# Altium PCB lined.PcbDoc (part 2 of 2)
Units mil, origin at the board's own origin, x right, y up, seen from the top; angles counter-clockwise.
Board outline 3500.17 x 4287.12 mil, 2 copper layers (Top Layer, Bottom Layer); 109 components, 117 nets, 494 pads, 325 vias.
Unrouted connection lines stored in the file: 3.
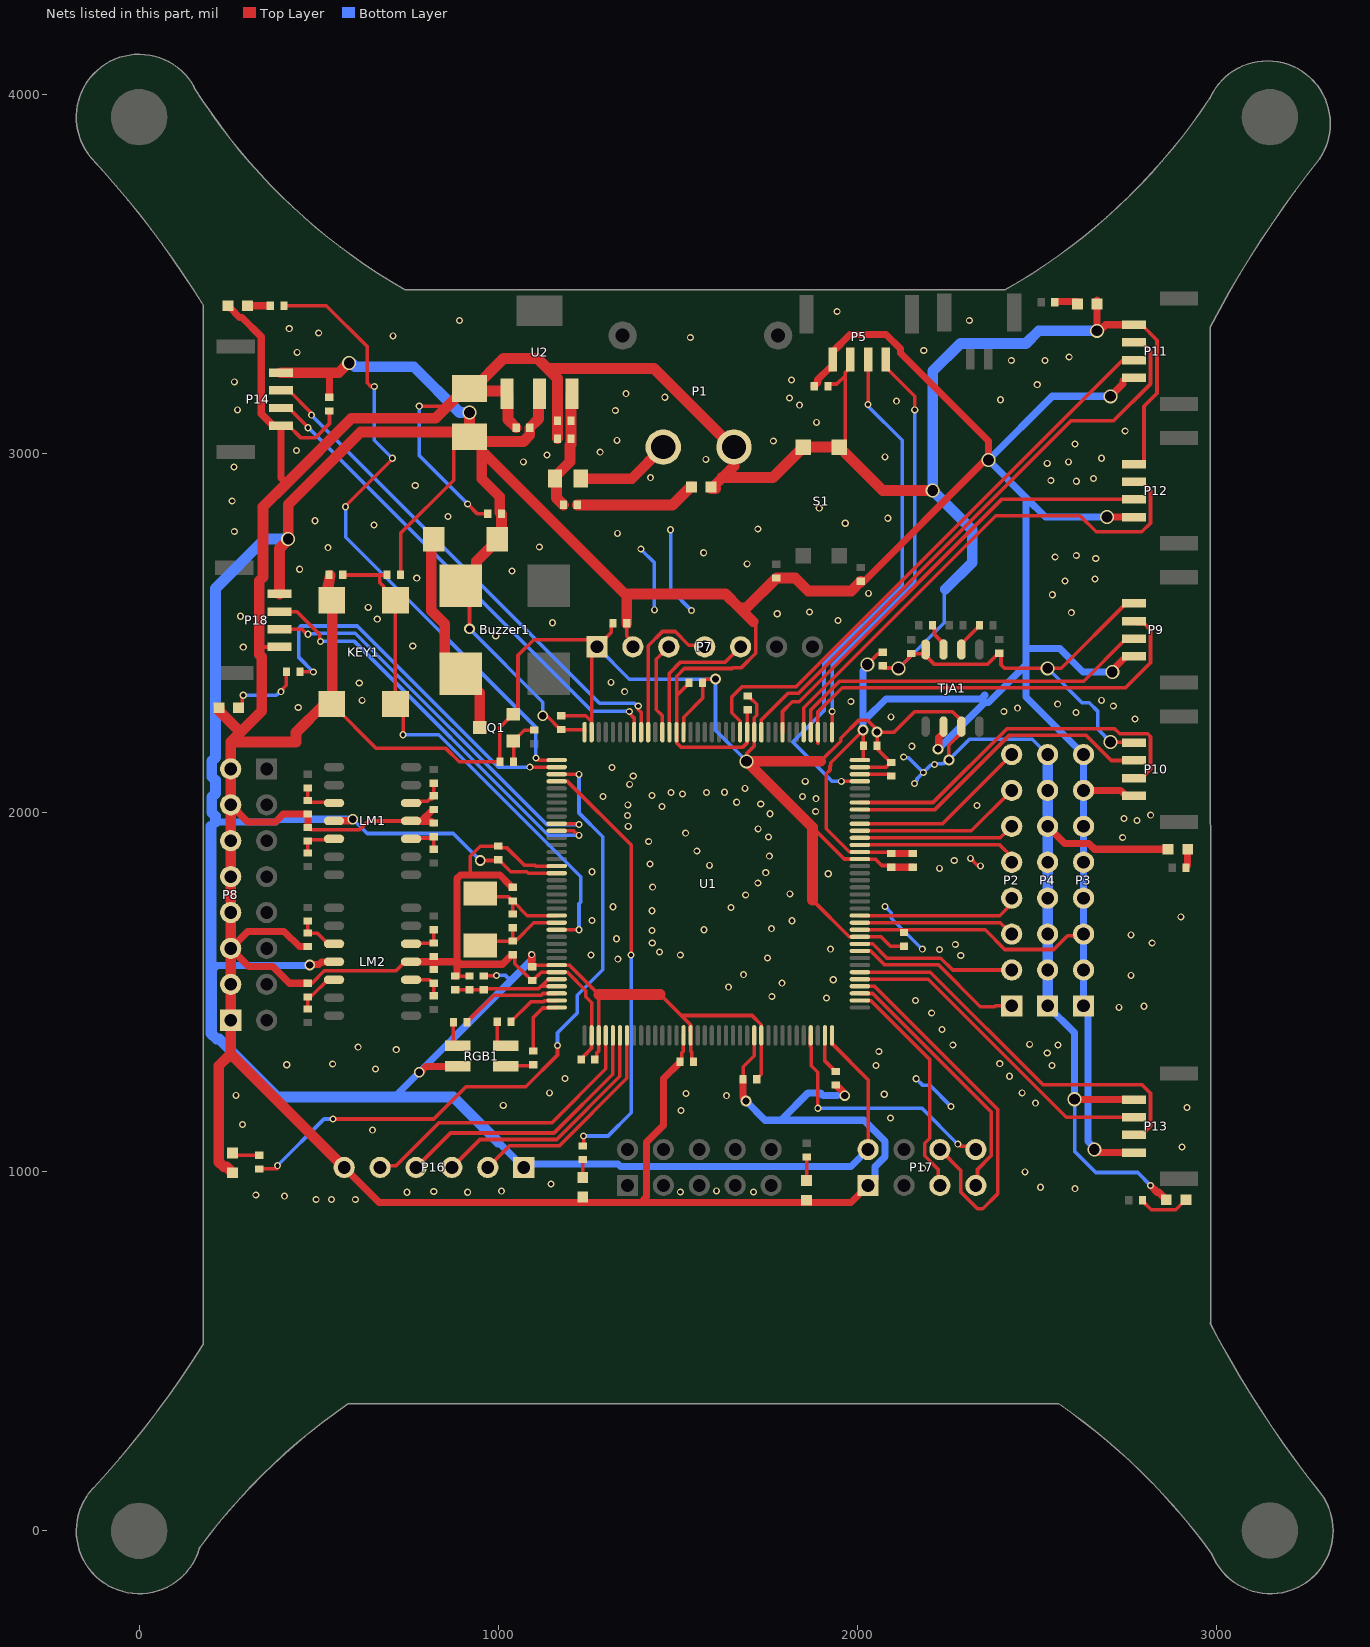
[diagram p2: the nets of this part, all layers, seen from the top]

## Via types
v1: diameter 19.68, hole 11.81, Top Layer to Bottom Layer, tented both sides, 293 vias
v2: diameter 30, hole 20, Top Layer to Bottom Layer, tented both sides, 16 vias
v3: diameter 39, hole 30, Top Layer to Bottom Layer, tented both sides, 16 vias

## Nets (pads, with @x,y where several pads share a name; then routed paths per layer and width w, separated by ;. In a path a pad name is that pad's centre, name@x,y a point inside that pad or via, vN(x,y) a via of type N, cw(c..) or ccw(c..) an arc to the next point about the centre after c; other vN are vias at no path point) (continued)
GND: C1.2 C2.2 C3.2 C4.2 C5.2 C6.2 C7.1 C8.1 C9.2 C10.1 C11.1 C12.1 C13.1 C14.1 C15.1 C16.1 C17.1 C18.1 C19.1 C20.1 C21.1 C22.1 C23.1 C24.1 C25.1 C26.1 C27.1 C28.1 C29.1 E1.2 KEY1.1 KEY1.2 LED1.2 LED2.2 LED3.2 LED4.2 LED5.2 LED6.2 LED7.2 LED8.2 LED9.2 LM1.11 LM2.11 P1.2 P4.1 P4.2 P4.3 P4.4 P4.5 P4.6 P4.7 P4.8 P5.3 P7.1 P8.1 P8.2 P8.3 P8.4 P8.5 P8.6 P8.7 P8.8 P9.4 P10.4 P11.4 P12.4 P13.4 P14.4 P16.6 P17.1 P18.4 Q1.1 R5.1 R6.1 R8.1 R9.1 R15.1 R16.1 R18.1 R19.1 R26.1 S1.1 S1.3 TJA1.3 TJA1.8 U1.16 U1.31 U1.38 U1.51 U1.61 U1.83 U1.94 U1.107 U1.120 U1.130 U1.143 U2.1 | length 25095.4
  Top Layer w10: 334.52,2467 339.99,2461.53 P18.4@390.98,2461.53 ; P14.4@395,3077.79 416.65,3077.79 450.83,3043.61 490,3043.61 530,3083.61 C28.1@530,3119 ; R19.1@469.23,1525.16 481.24,1525.16 515.71,1559.62 715.36,1559.62 740.55,1584.81 LM2.11@757.28,1584.81 ; R9.1@469.97,1959 471.78,1959 478.59,1952.19 613.88,1952.19 638.69,1977 LM1.11@757.28,1977 ; KEY1.1@536.42,2302.32 537.4,2302.32 660.72,2179 854.31,2179 891.31,2142 R26.1@1004.7,2142 1004.7,2237.84 1027.56,2260.7 1027.56,2261.69 1040.28,2274.4 Q1.1@1041.26,2274.4 1042.24,2274.4 1054.96,2287.12 1054.96,2438.16 1098.81,2482 1255,2482 P7.1@1275,2462 ; v1(780,3132) 850,3132 854.27,3127.73 ; C13.1@881.81,1545 C14.1@920,1545 ; v1(915,2859.51) 942.44,2832.06 C12.1@971,2832.06 ; 925,1826.8 922,1829.8 922,1878.6 950.3,1906.9 C22.1@1000,1906.9 1005,1901.9 1024.65,1901.9 1073.04,1853.5 1102.3,1853.5 1104.59,1851.21 U1.16@1162.76,1851.21 ; C2.2@1040,1604.5 1041.3,1604.5 1046.3,1599.5 1046.3,1579.5 1077.8,1548 1078.19,1548 1093.19,1533 C18.1@1095,1533 1096.81,1533 1111.81,1548 1112.2,1548 1119.79,1555.59 1162.41,1555.59 U1.31@1162.76,1555.94 1163.1,1555.59 1192.79,1555.59 1244.13,1504.25 1244.13,1487.16 1260.2,1471.09 1260.2,1382.78 1259.85,1382.43 1259.85,1343.75 1246,1329.9 1246,1329.51 1231,1314.51 C23.1@1231,1312.7 ; C19.1@1175,2270 1244.13,2270 1259.85,2254.28 1259.85,2224.59 U1.143@1260.2,2224.24 1260.2,2447.2 P7.1@1275,2462 ; C8.1@1320,2527 1315,2522 1315,2502 P7.1@1275,2462 ; C24.1@1506,1307 1511,1312 1511,1331.53 1515.76,1336.28 1515.76,1379.41 U1.51@1516.1,1379.76 ; U1.130@1516.1,2224.24 1516.45,2224.59 1516.45,2265.82 1569,2318.37 C25.1@1569,2362.24 1578.76,2372 v2(1605,2372) ; C26.1@1682,1257.58 1682,1292.53 1712.95,1323.49 U1.61@1712.95,1379.76 ; v3(1691.66,2143) 1691.66,2164.89 1712.61,2185.84 1712.61,2223.9 U1.120@1712.95,2224.24 1713.3,2224.59 1713.3,2264.71 1719.81,2271.23 1719.81,2302 1702.2,2319.61 1700,2319.61 C27.1@1695,2324.61 ; 1875,1756.92 1977.21,1654.71 2006.9,1654.71 U1.83@2007.24,1654.36 2066.1,1654.36 2092.46,1628 C20.1@2130,1628 ; 1875,1959.66 1963.7,1870.96 2007.18,1870.96 U1.94@2007.24,1870.9 2007.59,1870.55 2050.72,1870.55 2068.27,1853 2090,1853 C9.2@2095,1848 ; 1897.62,2143 1953.87,2199.25 1953.87,2207.3 2004.57,2258 2027.76,2258 2051.17,2234.59 2051.17,2228.42 v2(2055,2224.59) ; C7.1@1918,3187 1918,3188.78 1923,3193.78 1943,3193.78 1966.46,3217.24 ; S1.3@1949.8,3018.09 1966.46,3001.44 1966.46,3217.24 ; P5.3@1980.79,3262 1980.79,3240.35 1966.46,3226.02 1966.46,3217.24 ; U1.107@2007.24,2126.8 2079.99,2126.8 2093.19,2140 2055,2178.19 C21.1@2055,2187 v2(2055,2224.59) ; C29.1@2070.89,2404 2071.89,2403 2114,2403 v3(2115,2402) 2155.75,2442.75 2183.71,2442.75 TJA1.8@2190,2449.04 ; TJA1.8@2190,2454.48 TJA1.8@2190,2449.04 ; v2(2255,2147) 2255,2188.18 2290,2223.18 TJA1.3@2290,2239.92 2290,2256.65 2265.19,2281.46 2159.46,2281.46 2102.59,2224.59 v2(2055,2224.59) ; v1(2315,1873) 2334.15,1853.85 2341.15,1853.85 v1(2343,1852) ; v3(2667.5,3342) v3@2675,3342 ; v3(2705,2197) 2706.18,2195.82 2768.82,2195.82 P10.4@2770,2194.64 ; P9.4@2770,2582.71 2748.35,2582.71 2567.64,2402 v3(2530,2402) 2410,2402 2400,2412 2400,2439.2 C11.1@2395,2444.2 2393.19,2444.2 2361.93,2412.94 2214.81,2412.94 2190,2437.75 TJA1.8@2190,2449.04 ; P12.4@2770,2970.78 2791.65,2970.78 2798.46,2977.59 2798.46,3132.08 2834.46,3168.08 2834.46,3316.04 2791.65,3358.85 P11.4@2770,3358.85
  Top Layer w20: LED2.2@247.5,3412.06 266.64,3392.92 266.64,3391.9 279.54,3379 286.57,3379 340.17,3325.4 340.17,3110.97 373.35,3077.79 P14.4@395,3077.79 395,2932.1 410,2917.1 ; P8.7@255,2022 302.53,1974.47 379.86,1974.47 401.39,1996 R6.1@469.97,1996 R9.1@469.97,1959 ; R19.1@469.23,1525.16 419.06,1525.16 372.21,1572 305,1572 P8.3@255,1622 302.53,1669.53 403.72,1669.53 446.25,1627 R16.1@469.97,1627 ; P16.6@571,1012 668.53,914.47 1397.47,914.47 ; LM2.11@757.28,1584.81 825,1584.81 ; LM1.11@757.28,1977 757.98,1976.31 812.76,1976.31 818.19,1970.87 R8.1@820,1970.87 ; 786.82,1977.69 818.19,2009.06 R5.1@820,2009.06 ; R18.1@820,1563.16 821.81,1563.16 821.81,1581.62 825,1584.81 ; C13.1@880,1545 881.81,1545 881.81,1546.81 884.76,1549.76 884.76,1588.75 ; C2.2@1040,1604.5 1038.19,1604.5 1011.89,1578.2 895.3,1578.2 884.76,1588.75 ; C1.2@1040,1792.5 1038.19,1792.5 1018.84,1811.85 1018.84,1812.66 1004.7,1826.8 925,1826.8 895.3,1826.8 884.76,1816.26 884.76,1588.75 ; C24.1@1506,1307 1506,1305.19 1460.36,1259.55 1460.36,1129.58 1412.47,1081.69 1412.47,929.47 1397.47,914.47 ; C26.1@1682,1257.58 1682,1207.71 1690,1199.71 v2(1690,1197) ; C16.1@1939.77,1241.28 1941.58,1241.28 1962.85,1220 1962.85,1213.91 v2(1964.77,1212) ; P17.1@2030,962 1982.19,914.19 1942.81,914.19 1942.53,914.47 1397.47,914.47 ; C9.2@2095,1848 C17.1@2155,1848 ; P4.6@2530,1962 2577.53,1914.47 2644.74,1914.47 2661.09,1898.13 LED7.2@2865.5,1898.13 ; v3@2605,1201.21 P13.4@2770,1201.21 ; v3(2667.5,3342) LED6.2@2667.5,3416.94 LED6.2@2667.5,3426.94 ; v3@2675,3342 2691.85,3358.85 P11.4@2770,3358.85 ; v1(2816.46,962) 2835.38,943.06 2839.49,943.06 LED8.2@2860.48,922.06 ; 825,1584.81 880.82,1584.81 884.76,1588.75
  Top Layer w30: LED3.2@222.5,2292.06 222.5,2283.97 276.97,2229.5 287.5,2229.5 ; LED4.2@259.94,997.5 243.44,1014 235.47,1014 222,1027.47 222,1295 255,1328 ; KEY1.1@515.73,2302 436.85,2223.12 436.85,2197 255,2197 ; KEY1.2@525.98,2600.64 525.98,2628.56 C6.2@532.34,2661.35 ; KEY1.1@536.42,2302.32 537.84,2303.74 537.84,2590.26 KEY1.2@536.42,2591.69 ; P16.6@571,1012 255,1328 ; C3.2@1050,3072 1027.17,3094.83 1027.17,3163.93 U2.1@1024.45,3166.65 1024.45,3171.43 1021.73,3174.15 927.5,3174.15 E1.2@920,3181.65 ; C5.2@1165,3042 C4.2@1165,3092 1164.83,3092.17 1164.83,3209.38 1137.21,3237 ; LED1.2@1605,2902 1593.5,2902 1656.43,2964.93 1656.43,3014.57 1434,3237 1137.21,3237 ; 1623,2933.3 1765.01,2933.3 S1.1@1849.8,3018.09 S1.3@1949.8,3018.09 ; 1875,1756.92 1875,1959.66 v3(1691.66,2143) 1897.62,2143 ; S1.3@1966.46,3001.44 2070.89,2897 v3(2210,2897) ; 255,1328 P8.1@255,1422 P8.2@255,1522 P8.3@255,1622 P8.4@255,1722 P8.5@255,1822 P8.6@255,1922 P8.7@255,2022 P8.8@255,2122 255,2197 ; 255,2197 287.5,2229.5 ; 287.5,2229.5 341.15,2283.15 341.15,2433.56 334.52,2440.19 334.52,2467 334.52,2646.16 344.93,2656.56 344.93,2852.03 410,2917.1 591.32,3098.43 824.97,3098.43 854.27,3127.73 908.19,3181.65 E1.2@920,3181.65 ; E1.2@920,3181.65 931.81,3181.65 1014.74,3264.57 1109.64,3264.57 1137.21,3237
  Bottom Layer w10: v1(780,3132) 780,2994.51 v1(915,2859.51) ; P7.1@1275,2462 1365,2372 v2(1605,2372) 1605,2229.66 v3(1691.66,2143) ; v1(1397,2734) 1435,2696 v1(1435,2565) ; v1(1480,2788) 1480,2621 v1(1538,2563) ; v1(2077,1739) 2094.57,1721.43 2094.57,1706.43 v1(2181,1620) ; v3(2115,2402) 2242.16,2529.16 2242.16,2619.16 2245,2622 ; v1(2129,2155) 2130.85,2153.15 2142.56,2153.15 v1(2183.71,2112) ; v1(2159,2081) 2159,2083.62 2166.14,2090.76 2166.14,2094.43 v1(2183.71,2112) ; v1(2164,1259) 2181.57,1241.43 2201.57,1241.43 v1(2261,1182) ; P4.8@2530,2162 2487.47,2204.53 2312.53,2204.53 v2(2255,2147) 2249.59,2147 2238.44,2135.85 2216.66,2135.85 v1(2214.81,2134) 2212.96,2132.15 2203.85,2132.15 v1(2183.71,2112) ; v3(2530,2402) 2625.6,2306.4 2645.6,2306.4 2670,2282 2670,2232 v3(2705,2197) ; v3(2605,1202) 2605,1057 2664.07,997.93 2780.54,997.93 v1(2816.46,962)
  Bottom Layer w20: v2(1690,1197) 1743.28,1143.72 1790,1143.72 ; 1945,1212 1904.38,1212 1896.53,1219.84 1863.47,1219.84 1790,1146.38 1790,1143.72 ; P17.1@2030,962 2049.53,981.53 2049.53,1014.31 2077.53,1042.31 2077.53,1084.47 2018.28,1143.72 1790,1143.72 ; P4.1@2530,1462 2605,1387 v3(2605,1202)
  Bottom Layer w30: 2245,2622 2320,2697 2320,2787 v3(2210,2897) 2210,3229.84 2287.16,3307 2470,3307 2505,3342 v3(2667.5,3342) ; P4.1@2530,1462 P4.2@2530,1562 P4.3@2530,1662 P4.4@2530,1762 P4.5@2530,1862 P4.6@2530,1962 P4.7@2530,2062 P4.8@2530,2162
  other v1: 493,923 536,923 602,923 405,932 325,935 746,943 915,943 1507,944 1711,944 820.4,945 1009,946 1608,947 2606,953 2510,957 1147,966 2467,1000 2182,1010 2904,1069 650,1116 288,1132 2092.46,1150 1509,1171 2918,1179 1014,1185 2496,1191 1636,1212 270,1213 2075,1216 1523,1218 1143,1220 2459,1220 1186,1260 2424,1266 658,1286 2052,1296 2542,1296 411,1298 539,1300 2396.73,1301 2529,1331 2060,1334.64 716,1340 610,1347 2266,1353 2559,1353 2480,1355 2236,1396 2207,1442 2729,1458 2798,1461 2162,1477 1914,1484 1762,1488 1641,1514 1790,1525.16 1933,1534.81 2762,1547 1683,1549 1333,1592 1750,1595 2288,1602 1258,1604 1507,1604 1449,1612 2229,1619.13 1925,1620 2273,1633 1429,1637 2821,1637 1329,1649 2762,1660 1428,1672 1573,1674 1761,1677 1818,1699 1261,1700 2901,1710 1428,1727 1648,1736 1319.25,1738 1689,1771 1812,1774 1430,1792.5 1723,1804 1919,1830 1745,1833 1261,1835.5 2229,1845 1588,1853.5 1423,1857 2270,1867 1755,1879 1553,1893 1419,1920 2739,1931 1752.32,1932.37 1522,1943 1724,1955 1362,1962 2779,1978 2743,1984 1360,1992 2817,1993 1757,1997 1884,2003 1456,2017 2333,2020 1361,2022 1731,2024 1664,2029 1885,2039 1292,2045 1847,2045 1428,2048 1513,2052 1481,2056 1580,2056 1630,2057 1687,2067.75 1366,2079 1855,2087.43 1376,2102 1317,2126 2151.81,2185 2773,2261 2094,2267 2609,2279 2408,2281.46 2446,2291 443,2293 2713,2297 2558,2302.32 1982,2310 621,2313 2680,2313 1352,2337 613,2361 1314,2363 290,2461 762,2464 993,2492 1151,2529 1946,2535 663,2539 282,2547 1777,2554 2596,2557 1867,2559 638,2572 2543,2607 2031,2611 2578,2645 2662,2651 773,2653 1038.19,2673 447,2678 1693.27,2693 2664,2708 2551,2712 2610,2716 1572,2724 526,2738 1114.47,2740 1332,2778 265,2783 1723,2790 654,2801 1966.46,2806 490,2813 2085,2820 860,2825 1894,2848 259,2868 769,2911 2610,2923 2539,2925 2658,2931 1424,2933 264,2963 2529,2973 1070,2977 2588,2977 1578,2984 2680,2987 2077,2991 1136,2996 1284,3004 438,3009 2606,3027 1766,3035.35 1331,3037 2746,3063 1886,3087 1326,3120 274,3122 1839,3135 2109,3146 2399,3150 1811,3155 1464,3157 1356,3167 2501,3192 265,3200 1817,3205 2429,3259 2523,3259 2590,3269 440,3282 2185,3287 1535,3323 707,3328 500,3336 418,3348 892,3371 2312,3371 1944,3396
I2C1_SCL: P14.2 U1.136 | length 1438.7
  Top Layer w10: P14.2@395,3176.21 416.65,3176.21 478.15,3114.72 478.15,3108.85 v1(480,3107) ; v1(1390,2297) 1390,2287 1397.99,2279.01 U1.136@1397.99,2224.24
  Bottom Layer w10: v1(480,3107) 1282.16,2304.84 1379.54,2304.84 1387.38,2297 v1(1390,2297)
I2C1_SDA: P14.3 U1.137 | length 1384.2
  Top Layer w10: P14.3@395,3127 416.65,3127 470,3073.65 v1(470,3072) ; v1(1365,2282) 1365,2277 1378.31,2263.69 U1.137@1378.31,2224.24
  Bottom Layer w10: v1(470,3072) 471.85,3072 1261.85,2282 v1(1365,2282)
I2C2_SCL: P18.2 U1.11 | length 1169.7
  Top Layer w10: P18.2@390.98,2559.95 391.08,2559.86 439.45,2559.86 503.15,2496.16 503.15,2478.85 v1(505,2477) ; U1.11@1162.76,1949.64 1209.74,1949.64 1222.38,1937 v1(1225,1937)
  Bottom Layer w10: v1(505,2477) 599.6,2477 1139.6,1937 v1(1225,1937)
I2C2_SDA: P18.3 U1.10 | length 1124.8
  Top Layer w10: P18.3@390.98,2510.74 453.64,2510.74 467.38,2497 v1(470,2497) ; U1.10@1162.76,1969.32 1220.06,1969.32 1222.38,1967 v1(1225,1967)
  Bottom Layer w10: v1(470,2497) 471.85,2498.85 494.55,2498.85 495.54,2499.84 602.22,2499.84 1135.06,1967 v1(1225,1967)
IRQ: P17.8 U1.69 | length 699.1
  Top Layer w10: U1.69@1870.43,1379.76 1869.65,1379.01 1869.65,1349.29 1872.12,1346.82 1872.12,1295.35 1890.12,1277.35 v1(1890.12,1177) ; v1(2280,1077) 2282.62,1077 2288.23,1071.39 2320.61,1071.39 P17.8@2330,1062
  Bottom Layer w10: v1(1890.12,1177) 2180,1177 v1(2280,1077)
NetBuzzer1_2: Buzzer1.2 D1.2 Q1.3 | length 583.9
  Top Layer w30: D1.2@820,2762 813.24,2755.24 813.24,2563.42 851.24,2525.42 851.24,2431.06 Buzzer1.2@895.3,2387 948.74,2333.56 Q1.3@948.74,2237
NetC4_1: C4.1 C5.1 F1.1 R2.1 U2.3 | length 339.4
  Top Layer w30: R2.1@1182,2857 1162.54,2876.46 1162.54,2925.46 F1.1@1157.85,2930.15 1157.85,2935.46 1200,2977.61 1200,3023.26 1203,3026.26 C5.1@1203,3042 C4.1@1203,3092 1203,3164.09 U2.3@1205.55,3166.65
NetC15_2: C15.2 U1.106 | length 89.9
  Top Layer w10: U1.106@2007.24,2107.12 2007.59,2106.77 2090.23,2106.77 C15.2@2095,2102
NetC16_2: C16.2 U1.71 | length 112.6
  Top Layer w10: U1.71@1909.8,1379.76 1909.8,1308.57 1937.96,1280.42 C16.2@1936.81,1279.28
NetLED1_1: LED1.1 R2.2 | length 338.7
  Top Layer w30: R2.2@1220,2857 1485.56,2857 1535.56,2907 LED1.1@1538,2907
NetLED2_1: LED2.1 R30.1 | length 63
  Top Layer w20: LED2.1@302,3412 R30.1@365,3412
NetLED3_1: LED3.1 R31.1 | length 210.7
  Top Layer w10: LED3.1@277,2292 287,2302 287,2321.38 290,2324.38 v1(290,2327) ; v1(395,2337) 395,2339.62 410,2354.62 R31.1@410,2392
  Bottom Layer w10: v1(290,2327) 382.38,2327 392.38,2337 v1(395,2337)
NetLED4_1: LED4.1 R32.1 | length 77.5
  Top Layer w10: LED4.1@260,1052 266,1046 R32.1@335,1046
NetLED5_1: LED5.1 R33.1 | length 59.2
  Top Layer w10: LED5.1@1234.52,975 1235,975.48 R33.1@1235,1034
NetLED6_1: LED6.1 R34.1 | length 64.8
  Top Layer w20: R34.1@2550,3422 2550,3423.81 LED6.1@2613,3423.81
NetLED7_1: LED7.1 R35.1 | length 53.1
  Top Layer w20: R35.1@2914.98,1847 2914.98,1848.81 2919.24,1853.06 2919.24,1897.3 LED7.1@2920,1898.06
NetLED8_1: LED8.1 R36.1 | length 144.6
  Top Layer w10: R36.1@2794,920.5 2794,918.69 2818.62,894.06 2887.05,894.06 LED8.1@2914.98,922
NetLED9_1: LED9.1 R37.1 | length 66.2
  Top Layer w10: R37.1@1858.68,1041.62 LED9.1@1858.74,975.48 LED9.1@1858.74,975.48
NetLM1_3: LM1.3 R6.2 R7.1 | length 117.6
  Top Layer w10: R6.2@465,2036 465,2034 469.39,2029.61 540.11,2029.61 LM1.3@542.72,2027 ; R6.2@469.97,2034 R7.1@469.97,2069
NetLM1_5: LM1.5 R9.2 R12.1 | length 116.2
  Top Layer w10: R9.2@465,1921 R9.2@466.81,1921 ; R9.2@469.23,1921.73 R9.2@473.5,1926 ; R12.1@469.97,1887.9 R9.2@469.97,1921 473.36,1924.39 540.11,1924.39 LM1.5@542.72,1927
NetLM1_10: LM1.10 R8.2 R13.1 | length 103.5
  Top Layer w10: LM1.10@757.28,1927 759.89,1929.61 816.73,1929.61 R8.2@820,1932.87 R13.1@820,1898.06 ; R8.2@815.03,1934.87 R8.2@817.53,1932.37
NetLM1_12: LM1.12 R4.2 R5.2 | length 120
  Top Layer w10: LM1.12@757.28,2027 777.7,2027 782.76,2032.06 803.19,2032.06 818.19,2047.06 R5.2@820,2047.06 ; R5.2@815.03,2038 R5.2@820.98,2043.94 ; R4.2@820.98,2077.94 R5.2@820.98,2043.94 ; R5.2@822.2,2043 820.98,2043 R5.2@820.98,2043.94 ; R5.2@824.09,2047.06 R5.2@820.98,2043.94
NetLM2_3: LM2.3 R16.2 R17.1 | length 127.7
  Top Layer w10: R17.1@465,1702 465,1698.19 R17.1@466.81,1698.19 ; R17.1@469.97,1698.19 R16.2@469.97,1665 470.95,1664.02 496.78,1664.02 525.98,1634.81 LM2.3@542.72,1634.81 LM2.3@540.12,1637.41
NetLM2_5: LM2.5 R19.2 R20.1 | length 127
  Top Layer w10: R20.1@469.23,1453.35 R19.2@469.23,1487.16 478.33,1487.16 525.98,1534.81 LM2.5@542.72,1534.81
NetLM2_10: LM2.10 R18.2 R21.1 | length 101.9
  Top Layer w10: LM2.10@757.28,1534.81 808.54,1534.81 818.19,1525.16 R18.2@820,1525.16 R21.1@820,1490
NetLM2_12: LM2.12 R14.2 R15.2 | length 102.8
  Top Layer w10: LM2.12@757.28,1634.81 758.46,1635.98 818.83,1635.98 R15.2@820,1637.16 820,1669 R14.2@815.08,1673.92 ; R15.2@815.03,1637.16 R15.2@815.11,1637.24 ; R14.2@815.03,1673.92 R14.2@815.11,1674
NetQ1_2: Q1.2 R25.2 R26.2 | length 129.5
  Top Layer w10: R26.2@1042.7,2142 1042.7,2198.16 Q1.2@1041.26,2199.6 1042.24,2199.6 1072.65,2230 R25.2@1100,2230
NetR22_1: R22.1 TJA1.7 | length 80.6
  Top Layer w10: R22.1@2209,2522.2 2209,2520.39 2214.81,2514.58 2214.81,2496.41 2240,2471.22 TJA1.7@2240,2454.48
NetR23_1: R23.1 TJA1.6 | length 88.4
  Top Layer w10: TJA1.6@2290,2454.48 2290,2470.39 2340,2520.39 R23.1@2340,2522.2
NetR27_2: R27.2 RGB1.4 | length 85.2
  Top Layer w10: R27.2@997.17,1417.55 997.17,1360.31 1006.93,1350.54 RGB1.4@1021.07,1350.54
NetR28_1: R28.1 RGB1.2 | length 73
  Top Layer w10: R28.1@875,1417 875,1360.31 884.76,1350.54 RGB1.2@887.21,1350.54
NetR29_2: R29.2 RGB1.3 | length 78.4
  Top Layer w10: RGB1.3@1021.07,1293.46 1023.34,1295.73 1095.31,1295.73 R29.2@1097.58,1298
NRST: C6.1 KEY1.3 KEY1.4 R3.1 U1.25 | length 1460.3
  Top Layer w10: C6.1@567,2662 669.88,2662 ; R3.1@690,2662 669.88,2662 ; KEY1.4@693.88,2591.37 693.88,2617 669.88,2641 669.88,2662 ; KEY1.4@713.58,2591.69 KEY1.3@713.58,2302.32 738.58,2277.32 735,2273.73 v1(735,2217) ; U1.25@1162.76,1674.05 v1(1225,1674.05)
  Bottom Layer w10: v1(735,2217) 834.15,2217 1229.76,1821.38 1229.76,1751.41 1225,1746.64 v1(1225,1674.05)
OSC_IN: C1.1 R1.2 U1.23 x1.1 | length 275.4
  Top Layer w10: x1.1@950,1775.34 959.83,1765.51 1027.4,1765.51 1028.4,1764.5 1030,1764.5 C1.1@1040,1754.5 C1.1@1040.07,1754.44 ; R1.2@1040.13,1717.5 1040.07,1717.57 C1.1@1040.07,1754.44 ; U1.23@1162.76,1713.42 1081.09,1713.42 C1.1@1040.07,1754.44
OSC_OUT: C2.1 R1.1 U1.24 x1.2 | length 271
  Top Layer w10: x1.2@950,1642.5 C2.1@1040,1642.5 ; R1.1@1040.13,1679.5 1040.07,1679.44 1040.07,1642.57 C2.1@1040,1642.5 ; U1.24@1162.76,1693.73 1162.41,1693.39 1099.27,1693.39 1048.39,1642.5 C2.1@1040,1642.5
RES: P7.5 U1.132 | length 393.1
  Top Layer w10: U1.132@1476.73,2224.24 1476.73,2388.69 1507.51,2419.47 1632.47,2419.47 P7.5@1675,2462
RLED_1: R30.2 U1.1 | length 1793.6
  Top Layer w10: R30.2@403,3412 521.26,3412 635,3298.26 635,3197 645,3187 v1(655,3187) ; v1(575,2852.03) 575,2854.51 705,2984.51 v1(705,2987) ; v1(1105,2152) 1107.62,2152 1113.13,2146.49 U1.1@1162.76,2146.49
  Bottom Layer w10: v1(575,2852.03) 575,2767.02 1105,2237.01 v1(1105,2152) ; v1(655,3187) 655,3037 v1(705,2987)
RLED_2: R31.2 U1.2 | length 1058.5
  Top Layer w10: R31.2@448,2392 v1(485,2392) ; v1(1088,2126.8) U1.2@1162.76,2126.8
  Bottom Layer w10: v1(485,2392) 445,2432 445,2513.98 450.86,2519.84 607.67,2519.84 1000.71,2126.8 v1(1088,2126.8)
RLED_3: R32.2 U1.3 | length 1885.1
  Top Layer w10: R32.2@335,1008 383.38,1008 v1@387.38,1012 ; v1(540,1147) 820.4,1147 910.44,1237.04 1076.82,1237.04 1165,1325.22 v1(1165,1352) ; U1.3@1162.76,2107.12 1162.93,2106.94 1224.83,2106.94 v1(1225,2106.77)
  Bottom Layer w10: v1(385,1017) 515,1147 v1(540,1147) ; v1(1165,1352) 1165,1387 1220,1442 1220,1492 1290.86,1562.86 1290.86,1933.45 1225,1999.3 v1(1225,2106.77)
RLED_4: R33.2 U1.4 | length 1214.4
  Top Layer w10: U1.4@1162.76,2087.43 1163.1,2087.09 1192.79,2087.09 1370,1909.88 v1(1370,1604) ; R33.2@1235,1072 1237.62,1074.62 v1(1237.62,1099.62)
  Bottom Layer w10: v1(1237.62,1099.62) 1305.61,1099.62 1370,1164.01 v1(1370,1604)
SPI1_MISO: P16.3 U1.42 | length 686.7
  Top Layer w10: P16.3@871,1012 949,1090 1162.54,1090 1338.59,1266.05 1338.59,1379.41 U1.42@1338.94,1379.76
SPI1_MOSI: P16.2 U1.43 | length 609.7
  Top Layer w10: P16.2@971,1012 1031,1072 1170,1072 1358.28,1260.28 1358.28,1379.41 U1.43@1358.62,1379.76
SPI1_NSS: P16.5 U1.40 | length 835.5
  Top Layer w10: P16.5@671,1012 675.67,1016.67 715.53,1016.67 835.86,1137 1150,1137 1299.57,1286.57 U1.40@1299.57,1379.76
SPI1_SCK: P16.4 U1.41 | length 763.6
  Top Layer w10: P16.4@771,1012 867,1108 1155.09,1108 1318.91,1271.82 1318.91,1379.41 U1.41@1319.25,1379.76
SPI2_MISO: P17.7 U1.75 | length 724.6
  Top Layer w10: U1.75@2007.24,1496.88 2007.59,1496.54 2043.05,1496.54 2372.53,1167.06 2372.53,1044.38 2334.67,1006.53 2334.67,966.67 P17.7@2330,962
SPI2_MOSI: P17.6 U1.76 | length 1044
  Top Layer w10: U1.76@2005.43,1516.22 2048.82,1516.22 2390.53,1174.51 2390.53,938.39 2349.14,897 2334.86,897 2287.47,944.38 2287.47,1004.53 P17.6@2230,1062
SPI2_SCK: P17.5 U1.74 | length 618.7
  Top Layer w10: U1.74@2025,1476.42 2025.43,1476.85 2037.28,1476.85 2201.43,1312.7 2201.43,1093.57 2187.47,1079.62 2187.47,1044.38 2225.33,1006.53 2225.33,966.67 P17.5@2230,962
SPI3_CLK: P7.3 U1.133 | length 258.9
  Top Layer w10: U1.133@1457.05,2224.24 1457.05,2270.54 1440.47,2287.12 1440.47,2427.47 P7.3@1475,2462
SPI3_MOSI: P7.4 U1.135 | length 432
  Top Layer w10: U1.135@1417.68,2224.24 1417.68,2464.82 1457.38,2504.53 1492.62,2504.53 1530.47,2466.67 1570.33,2466.67 P7.4@1575,2462
SWCLK: P5.1 U1.109 | length 1190
  Top Layer w10: U1.109@1929.49,2246.49 U1.109@1929.49,2224.24 1930,2223.73 1930,2246.49 v1(1930,2282) ; P5.1@2079.21,3262 2079.21,3240.35 2160,3159.56 v1(2160,3122)
  Bottom Layer w10: v1(1930,2282) 1930,2411.54 2160,2641.54 v1(2160,3122)
SWDIO: P5.2 U1.105 | length 1485.5
  Top Layer w10: v1(1955.43,2087.43) U1.105@2007.24,2087.43 U1.105@2007.59,2087.78 ; v1(2030,3137) P5.2@2030,3262 P5.2@2030,3283.65
  Bottom Layer w10: v1(1955.43,2087.43) 1929.57,2087.43 1820,2197 1907.16,2284.16 1907.16,2414.16 2125,2632 2125,3037 2030,3132 v1(2030,3137)
TIM3_CH1: P2.5 U1.96 | length 451.5
  Top Layer w10: U1.96@2007.24,1910.27 2396.73,1910.27 2430,1877 P2.5@2430,1862
TIM3_CH2: P2.6 U1.97 | length 436
  Top Layer w10: U1.97@2007.24,1929.95 2397.95,1929.95 2417.5,1949.5 P2.6@2430,1962
TIM3_CH3: P2.7 U1.98 | length 469.3
  Top Layer w10: U1.98@2007.24,1949.64 2317.64,1949.64 2417.5,2049.5 P2.7@2430,2062
TIM3_CH4: P2.8 U1.99 | length 502.6
  Top Layer w10: U1.99@2007.24,1969.32 2237.32,1969.32 2417.5,2149.5 P2.8@2430,2162
TIM4_CH1: P2.1 U1.81 | length 488.3
  Top Layer w10: U1.81@2007.24,1614.99 2037.01,1614.99 2075,1577 2225,1577 2342.57,1459.43 2382.43,1459.43 2385,1462 P2.1@2430,1462
TIM4_CH2: P2.2 U1.82 | length 460.4
  Top Layer w10: U1.82@2000.78,1634.68 U1.82@2007.24,1634.68 U1.82@2020.78,1634.68 ; U1.82@2020,1635.46 U1.82@2020.78,1634.68 ; P2.2@2430,1562 2265.46,1562 2232.46,1595 2082.46,1595 2042.78,1634.68 U1.82@2020.78,1634.68
TIM4_CH3: P2.3 U1.85 | length 435.9
  Top Layer w10: U1.85@2007.24,1693.73 2398.27,1693.73 P2.3@2430,1662
TIM4_CH4: P2.4 U1.86 | length 451.7
  Top Layer w10: U1.86@2007.24,1713.42 2396.42,1713.42 2430,1747 P2.4@2430,1762
TIM5_CH1_B: R28.2 U1.34 | length 282.8
  Top Layer w10: R28.2@913,1417 988,1492 1119.65,1492 1124.19,1496.54 1162.41,1496.54 U1.34@1162.76,1496.88
TIM5_CH2_G: R27.1 U1.35 | length 152.3
  Top Layer w10: R27.1@1035.17,1417.55 1091.62,1474 1127.11,1474 1129.96,1476.85 1162.41,1476.85 U1.35@1162.76,1477.2
TIM5_CH3_R: R29.1 U1.36 | length 170.3
  Top Layer w10: R29.1@1097.58,1336 1097.58,1429.58 1124,1456 1134.56,1456 1135.73,1457.17 1162.41,1457.17 U1.36@1162.76,1457.51
UART4_RX: P9.2 U1.112 | length 1043.6
  Top Layer w10: U1.112@1870.43,2224.24 1870.78,2224.59 1870.78,2286.61 1950.45,2366.28 2630.34,2366.28 2748.35,2484.28 P9.2@2770,2484.28
UART4_TX: P9.3 U1.111 | length 1248.7
  Top Layer w10: U1.111@1890.12,2224.24 U1.111@1890.12,2224.37 ; U1.111@1890.9,2224.37 1890.9,2193.78 1890.46,2194.21 1890.46,2224.02 U1.111@1890.12,2224.37 ; P9.3@2770,2533.5 2776.81,2526.69 2798.69,2526.69 2816.46,2508.91 2816.46,2417.88 2746.87,2348.28 1957.9,2348.28 1890.12,2280.49 U1.111@1890.12,2224.37
UART5_RX: P12.2 U1.116 | length 1280.6
  Top Layer w10: U1.116@1791.69,2224.24 1791.69,2282 1818.97,2309.27 1838.18,2309.27 2401.27,2872.35 P12.2@2770,2872.35
UART5_TX: P12.3 U1.113 | length 1452.9
  Top Layer w10: U1.113@1850.75,2224.24 1850.75,2292.04 2385.71,2827 2620,2827 2665,2782 2792.52,2782 2816.46,2805.95 2816.46,2896.76 2791.65,2921.57 P12.3@2770,2921.57 P12.3@2748.35,2921.57
USART1_RX: P10.2 U1.102 | length 1051.3
  Top Layer w10: U1.102@2007.24,2028.38 2210.78,2028.38 2416.58,2234.18 2716.42,2234.18 2731.15,2219.45 2808.85,2219.45 2816.46,2211.83 2816.46,2121.02 2791.65,2096.21 P10.2@2770,2096.21
USART1_TX: P10.3 U1.101 | length 878
  Top Layer w10: U1.101@2007.24,2008.69 2216.55,2008.69 2424.04,2216.18 2635.96,2216.18 2706.72,2145.43 P10.3@2770,2145.43
USART2_RX: P11.2 U1.122 | length 1616.2
  Top Layer w10: U1.122@1673.58,2224.24 1673.58,2254.58 1650,2278.16 1650,2322 1678.2,2350.2 1828.2,2350.2 2738.43,3260.43 P11.2@2770,3260.43
USART2_TX: P11.3 U1.119 | length 1653.2
  Top Layer w10: U1.119@1732.64,2224.24 1732.98,2224.59 1732.98,2258.94 1806.24,2332.2 1835.66,2332.2 2595.46,3092 2714.45,3092 2816.46,3194.02 2816.46,3284.83 2791.65,3309.64 P11.3@2770,3309.64
USART3_RX: P13.2 U1.78 | length 1096.6
  Top Layer w10: U1.78@2007.24,1555.94 2203,1555.94 2516.94,1242 2792.87,1242 2816.46,1218.41 2816.46,1127.6 2791.65,1102.79 P13.2@2770,1102.79
USART3_TX: P13.3 U1.77 | length 921.9
  Top Layer w10: U1.77@2007.24,1536.25 2197.23,1536.25 2581.49,1152 P13.3@2770,1152
VCC: Buzzer1.1 C3.1 C7.2 C8.2 C9.1 C12.2 C17.2 C18.2 C19.2 C20.2 C21.2 C22.2 C23.2 C24.2 C25.2 C26.2 C27.2 C28.2 C29.2 D1.1 E1.1 LM1.4 LM2.4 P3.1 P3.2 P3.3 P3.4 P3.5 P3.6 P3.7 P3.8 P5.4 P7.2 P9.1 P10.1 P11.1 P12.1 P13.1 P14.1 P16.1 P17.2 P18.1 R3.2 R10.2 R11.1 R38.1 RGB1.1 TJA1.2 U1.17 U1.30 U1.39 U1.52 U1.62 U1.72 U1.84 U1.95 U1.108 U1.121 U1.131 U1.144 U2.2 | length 20343.7
  Top Layer w10: R3.2@728,2662 728,2777.81 875.79,2925.6 875.79,3014.6 E1.1@908.19,3047 ; Buzzer1.1@895.3,2632 920,2607.3 v2(920,2512) ; v2(950,1867) 999.91,1867 1001.81,1868.9 1035.2,1835.5 1079.46,1835.5 1083.44,1831.53 U1.17@1162.76,1831.53 ; R38.1@960,1545 960.91,1545.91 994.09,1545.91 v1(995,1546.81) ; C18.2@1095,1571 1099.28,1575.28 1162.41,1575.28 U1.30@1162.76,1575.62 1163.1,1575.28 1198.56,1575.28 1279.88,1493.96 U1.39@1279.88,1379.76 1279.54,1379.41 1279.54,1336.28 1274,1330.75 1274,1317.7 C23.2@1269,1312.7 ; v2(1124,2270) 1134.8,2270 1173.64,2231.16 1240.51,2231.16 U1.144@1240.51,2224.24 ; C8.2@1358,2527 1358,2492.27 1375,2475.27 P7.2@1375,2462 ; 1451.28,1493.96 1510,1435.23 ; C25.2@1531,2362.24 1531,2360.43 1496.76,2326.19 ; C24.2@1544,1307 1539,1312 1539,1333.42 1536.13,1336.28 1536.13,1391.31 1535.44,1392 1535.44,1409.79 1510,1435.23 ; C27.2@1695,2286.61 1693.61,2285.23 1693.61,2227.35 1693.27,2227 U1.121@1693.27,2224.24 1692.92,2223.9 1692.92,2194.21 1681.41,2182.7 1508.27,2182.7 1496.76,2194.21 1496.76,2223.9 U1.131@1496.42,2224.24 1496.76,2224.59 1496.76,2326.19 ; 1710,2532 1717.53,2524.47 1717.53,2444.38 1677.34,2404.2 1654.83,2404.2 1652.1,2401.47 1518.28,2401.47 1496.76,2379.96 1496.76,2326.19 ; C26.2@1720,1257.58 1720,1259.39 1732.64,1272.03 U1.62@1732.64,1379.76 1732.29,1380.1 1732.29,1409.79 1706.85,1435.23 1510,1435.23 ; U1.72@1929.49,1379.76 1929.49,1357.12 2030,1256.61 P17.2@2030,1062 ; U1.84@2007.24,1674.05 2355.94,1674.05 2410.86,1619.13 2547.28,1619.13 2585.47,1657.33 2625.33,1657.33 P3.3@2630,1662 ; U1.108@2007.24,2146.49 2016.16,2146.49 2017,2147.32 2016.16,2148.16 v2(2016.16,2230) 1925.62,2139.45 1925.62,2131.4 1924,2129.78 1924,2119 1913.19,2108.19 1913.19,1954.95 1977.21,1890.93 2006.9,1890.93 U1.95@2007.24,1890.58 2007.59,1890.24 2090.76,1890.24 C9.1@2095,1886 ; v3(2027.76,2412.94) 2056.82,2442 2065.89,2442 C29.2@2070.89,2447
  Top Layer w20: v2(475,1575.62) 476.91,1577.54 501.09,1577.54 507.68,1584.12 542.02,1584.12 LM2.4@542.72,1584.81 ; 520,3225.43 530,3215.43 C28.2@530,3157 ; LM1.4@542.72,1977 543.41,1977.69 587.99,1977.69 592.29,1982 v2(595,1982) ; v2(780,1277) 782.71,1277 799.16,1293.46 RGB1.1@887.21,1293.46 ; v1(1093.19,1604.5) 1093.19,1571 C18.2@1095,1571 ; C7.2@1880,3187 1880,3188.81 1890,3198.81 1890,3206.27 1922.27,3238.54 1929.76,3238.54 1931.57,3240.35 P5.4@1931.57,3262 1931.57,3283.65 1979.92,3332 2079.94,3332 2119.97,3291.97 2119.97,3280.37 2365,3035.35 v3(2365,2982) 2356.43,2982 R11.1@2011.62,2637.2 ; C9.1@2095,1886 C17.2@2155,1886 ; v2(2225,2177) 2226.91,2178.91 2226.91,2209.12 2240,2222.2 TJA1.2@2240,2239.92 ; P3.7@2630,2062 2733.35,2062 2748.35,2047 P10.1@2770,2047 ; v3(2660,1062) 2665.14,1062 2673.57,1053.57 P13.1@2770,1053.57 ; v3(2695,2823.14) P12.1@2770,2823.14 ; v3(2705,3159.56) 2740,3194.56 2740,3202.87 2748.35,3211.21 P11.1@2770,3211.21 ; v3@2710,2401.4 2714.67,2401.4 2748.35,2435.07 P9.1@2770,2435.07
  Top Layer w30: P18.1@390.98,2609.17 390.98,2735.55 415,2759.56 v3(415,2762) 415,2858 617.43,3060.43 E1.1@920,3060.43 ; P14.1@395,3225.43 520,3225.43 555.99,3225.43 582.56,3252 v3(585,3252) ; Buzzer1.1@895.3,2632 939.36,2676.06 939.36,2700.17 997.17,2757.98 D1.1@997.17,2762 1009,2773.83 C12.2@1009,2832.06 1004,2837.06 1004,2880.09 954.21,2929.88 954.21,3007.79 ; v3(920,3114.72) E1.1@920,3060.43 ; U2.2@1115,3166.65 1112.28,3163.93 1112.28,3096.28 C3.1@1088,3072 1088,3051.57 1070.43,3034 E1.1@944.81,3034 ; 1279.88,1493.96 1451.28,1493.96 ; C8.2@1358,2527 1358,2604 954.21,3007.79 ; 1358,2609 1633,2609 1671.5,2570.5 ; 1710,2532 1671.5,2570.5 ; R11.1@2009.8,2644.64 1982.81,2617.65 1863.27,2617.65 1827.27,2653.64 R10.2@1774.8,2653.64 1691.66,2570.5 1671.5,2570.5 ; E1.1@920,3060.43 E1.1@920,3047 931.81,3047 E1.1@944.81,3034 ; E1.1@944.81,3034 954.21,3024.6 954.21,3007.79
  Bottom Layer w10: v2(595,1982) 635,1942 875,1942 v2(950,1867) ; v2(920,2512) 1124,2308 v2(1124,2270) ; v1(995,1546.81) 1020.19,1546.81 1035,1532
  Bottom Layer w20: 200,1962 212.47,1974.47 381.15,1974.47 388.67,1982 v2(595,1982) ; 207.47,1385.02 207.47,1564.42 217.53,1574.47 473.85,1574.47 v2(475,1575.62) ; 710,1208.27 711.27,1208.27 1035,1532 1093.19,1590.19 v1(1093.19,1604.5) ; 1000,1083 P16.1@1071,1012 1081,1022 1332.79,1022 1340.31,1014.47 1982.47,1014.47 P17.2@2030,1062 ; v2(2016.16,2230) 2016.16,2396.2 2027.76,2407.8 v3(2027.76,2412.94) ; 2025,2262 2080,2317 2345,2317 2355,2327 ; v2@2226.35,2175.65 2225,2174.29 v2(2225,2177) 2355,2307 2365,2307 2470,2412 ; v3(2660,1062) 2660,1067.14 2642.5,1084.64 2642.5,1449.5 P3.1@2630,1462 P3.2@2630,1562 P3.3@2630,1662 P3.4@2630,1762 P3.5@2630,1862 P3.6@2630,1962 P3.7@2630,2062 P3.8@2630,2162 2470,2322 2470,2412 ; v3(2695,2823.14) 2523.86,2823.14 2470,2877 ; v3(2705,3159.56) 2542.56,3159.56 v3(2365,2982) 2470,2877 ; v3(2710,2392) 2628.67,2392 2563.67,2457 2475,2457 2470,2462 ; 2470,2412 2470,2462 ; 2470,2462 2470,2877
  Bottom Layer w30: 200,1962 200,1385.42 215.95,1369.47 223.02,1369.47 384.22,1208.27 710,1208.27 ; 212.47,1974.47 212.47,1990.24 202.47,2000.24 202.47,2043.76 212.47,2053.76 212.47,2090.24 202.47,2100.24 202.47,2143.76 212.47,2153.76 212.47,2624.47 350,2762 v3(415,2762) ; v3@591.5,3252 601.5,3242 765,3242 892.28,3114.72 v3(920,3114.72) ; 711.27,1208.27 874.73,1208.27 1000,1083
VCC_IN: F1.2 P1.1 | length 266.2
  Top Layer w30: F1.2@1229.85,2930.15 1371.57,2930.15 P1.1@1459.57,3018.15
VDDA: C13.2 C14.2 R38.2 U1.32 U1.33 | length 337.2
  Top Layer w10: C13.2@880,1507 C14.2@920,1507 R38.2@960,1507 963,1510 1112.2,1510 1118.76,1516.57 1120.43,1516.57 ; U1.33@1162.76,1516.57 1120.43,1516.57 ; U1.32@1162.76,1536.25 1140.12,1536.25 1120.43,1516.57
pads on no net: Buzzer1.3 Buzzer1.4 P1.0 P5.0 P9.0 P10.0 P11.0 P12.0 P13.0 P14.0 P15.0 P18.0 TJA1.5 U1.5 U1.6 U1.7 U1.8 U1.9 U1.12 U1.26 U1.27 U1.28 U1.29 U1.37 U1.44 U1.45 U1.49 U1.50 U1.53 U1.54 U1.55 U1.56 U1.57 U1.68 U1.79 U1.80 U1.87 U1.88 U1.93 U1.100 U1.110 U1.114 U1.115 U1.117 U1.118 U1.123 U1.124 U1.125 U1.126 U1.127 U1.134 U1.140 U1.141 U1.142 U2.4

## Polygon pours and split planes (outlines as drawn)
GND on Top Layer "Top Layer-GND" (solid, remove dead copper, pour order 10): 209,3446 2942,3446 2942,876 2945,873 196,873 196,3433
GND on Bottom Layer "Bottom Layer-GND" (solid, remove dead copper, pour order 14): 209,3445 2942,3445 2942,875 2945,872 196,872 196,3432

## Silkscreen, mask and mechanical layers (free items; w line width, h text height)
Top Overlay:
  drawing of 4116 lines, arcs and shapes, not listed
  text "92_PG7" at 2535,3462 h30
  text "1_PE2" at 218,3448 h30
  text "-" at 1765,3392 h60
  text "+" at 1315,3390 h60
  text "I2C1" at 380,3289 h30
  text "+ SCL SDA -" at 463,3256 h20 r270
  text "USART2" at 2661,3201 h30 r90
  text "+ R T -" at 2716,3192 h30 r90
  text "+ - SWD SCK" at 1889,3128 h30
  text "H L" at 2311,3128 h30
  text "0  0" at 1841,3072 h30
  text "BOOT" at 2054,2846 h60
  text "UART5" at 2655,2816 h30 r90
  text "POWER" at 1427.93,2789 h60
  text "+ R T -" at 2709,2788 h30 r90
  text "Buzzer" at 1051,2779 h30
  text "139_TIM10_CH1" at 1048,2731 h30
  text "RST" at 527,2708 h60
  text "I2C2" at 358,2670 h30
  text "1  1" at 1852,2649 h30
  text "OLED" at 1459,2633 h60
  text "+ SCL SDA -" at 453,2632 h20 r270
  text "SPI3     132 129 128" at 1351,2572 h30
  text "PG_15 _14 _13" at 1557,2527 h30
  text "UART4" at 2659,2445 h30 r90
  text "+ R T -" at 2709,2416 h30 r90
  text "2_PE3" at 197,2326 h30
  text "P - +" at 2388,2233 h60
  text "GND" at 215,2188 h30
  text "ADC3" at 310,2187 h30
  text "TIM3" at 2229,2168 h30
  text "99_CH4" at 2199,2124 h30
  text "9" at 418,2107 h20
  text "98_CH3" at 2197,2046 h30
  text "14" at 416,2009 h20
  text "97_CH2" at 2196,1949 h30
  text "15" at 416,1912.06 h20
  text "USART1" at 2734,1850 h30 r90
  text "96_CH1" at 2197,1845 h30
  text "+ R T -" at 2789,1821 h30 r90
  text "4" at 417,1808 h20
  text "TIM4" at 2230,1790 h30
  text "91_PG6" at 2788,1780 h30
  text "86_CH4" at 2195.33,1747 h30
  text "5" at 418,1710.19 h20
  text "85_CH3" at 2196.33,1644 h30
  text "6" at 417,1608 h20
  text "82_CH2" at 2196.33,1546 h30
  text "7" at 418,1510 h20
  text "81_CH1" at 2201,1448 h30
  text "8" at 416,1416 h20
  text "34_T5C1_B" at 577,1334 h30
  text "35_T5C2_G" at 576,1289 h30
  text "36_T5C3_R" at 576,1247 h30
  text "47 58 60 64 66" at 1323,1190 h35
  text "46 59 63 65 67" at 1322.33,1130 h35
  text "NRF24L01" at 2070,1129 h30
  text "- NSS SCK MISO MOSI +" at 569,1078 h25
  text "USART3" at 2658,1061 h30 r90
  text "+ R T -" at 2713,1032 h30 r90
  text "3_PE4" at 224,961 h30 r90
  text "90_PG5" at 2788,958 h30
  text "4_PE5" at 1187.33,918 h30 r90
  text "89_PG4" at 1923.67,911 h30 r90
  text "Designed" at 2807,341 h30
  text "by OuyJy" at 2787,279 h30
Mechanical 1:
  lines w10: -129,3826 cw(c-2129,1980.08) 184.17,3414.18 183,520 ; -125.89,3822.64 cw(c0,3937) 148.94,4019.11 ; -125.1,115.22 ccw(c0,0) 163.12,-48.15 ; -124.17,115.62 ccw(c-2129,1966) 181.15,514.65 ; 147,4020 ccw(c1571.31,4910.32) 737.85,3452.01 ; 162,-47 cw(c1570.21,-1079.6) 578.51,357.71 ; 583,359 970.5,359 2557.27,359 ; 733,3451 1369,3451 ; 1362,3451 2410.1,3451 ; 2410.1,3449.65 ccw(c1584.9,4910.46) 2985,3986 ; 2557.27,362.39 cw(c1564,-1088) 2991.23,-61.74 ; 2977.49,576.82 ccw(c5634.72,1965.17) 3278,112 ; 2979,581 2977.36,3353.75 cw(c5629.85,1961.54) 3282.94,3823.25 ; 2985.81,3985.82 cw(c3142.11,3918.77) 3284,3825 ; 2992.78,-64.85 ccw(c3150,0) 3278.45,111.47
